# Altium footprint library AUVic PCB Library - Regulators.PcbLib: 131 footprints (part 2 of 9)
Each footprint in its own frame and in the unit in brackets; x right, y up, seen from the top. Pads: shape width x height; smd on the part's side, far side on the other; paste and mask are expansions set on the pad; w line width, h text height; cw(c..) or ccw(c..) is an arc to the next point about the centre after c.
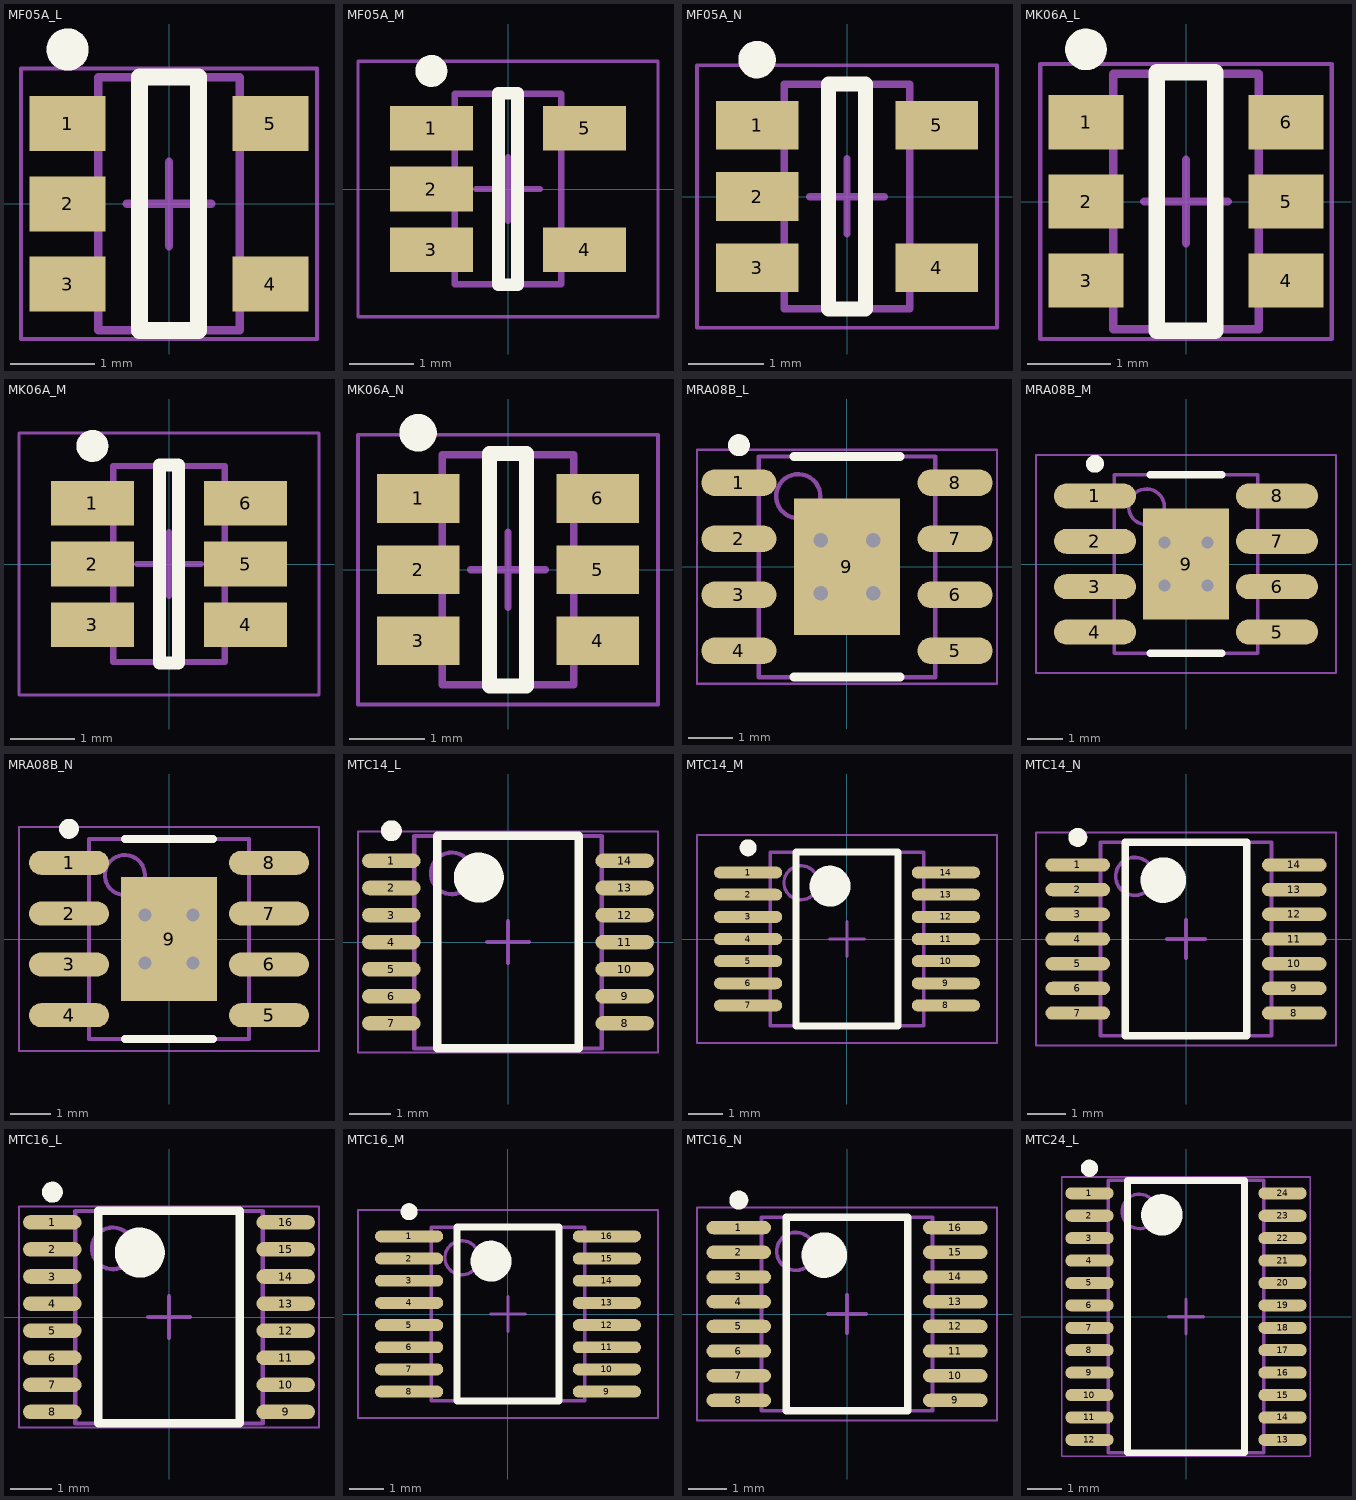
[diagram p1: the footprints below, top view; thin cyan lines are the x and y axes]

## MF05A_L [mm] "SOT23, 5-Leads, Body 2.9x1.6mm, Pitch 0.95mm, Lead Span 2.8mm, IPC High Density"
height 1.19
pads (5):
  rect 0.9x0.65 smd: 1(-1.2,0.95) 2(-1.2,0) 3(-1.2,-0.95) 4(1.2,-0.95) 5(1.2,0.95)
Top Overlay:
  circle w0.25: c-1.2,1.825 r0.125
  lines w0.2: -0.35,-1.5 -0.35,1.5 0.35,1.5 0.35,-1.5 -0.35,-1.5
Mechanical 13:
  lines w0.1: -0.835,-1.495 0.835,-1.495 0.835,1.495 -0.835,1.495 -0.835,-1.495
Mechanical 15:
  lines w0.05: -1.75,-1.6 1.75,-1.6 1.75,1.6 -1.75,1.6 -1.75,-1.6
  lines w0.1: -0.5,0 0.5,0 ; 0,-0.5 0,0.5
3D body: height 1.19, standoff 0.05, extent -0.835,-1.495 0.835,1.495

## MF05A_M [mm] "SOT23, 5-Leads, Body 2.9x1.6mm, Pitch 0.95mm, Lead Span 2.8mm, IPC Low Density"
height 1.19
pads (5):
  rect 1.3x0.7 smd: 1(-1.2,0.95) 2(-1.2,0) 3(-1.2,-0.95) 4(1.2,-0.95) 5(1.2,0.95)
Top Overlay:
  circle w0.25: c-1.2,1.85 r0.125
  lines w0.2: -0.15,-1.5 -0.15,1.5 0.15,1.5 0.15,-1.5 -0.15,-1.5
Mechanical 13:
  lines w0.1: -0.835,-1.495 0.835,-1.495 0.835,1.495 -0.835,1.495 -0.835,-1.495
Mechanical 15:
  lines w0.05: -2.35,-2 2.35,-2 2.35,2 -2.35,2 -2.35,-2
  lines w0.1: -0.5,0 0.5,0 ; 0,-0.5 0,0.5
3D body: height 1.19, standoff 0.05, extent -0.835,-1.495 0.835,1.495

## MF05A_N [mm] "SOT23, 5-Leads, Body 2.9x1.6mm, Pitch 0.95mm, Lead Span 2.8mm, IPC Medium Density"
height 1.19
pads (5):
  rect 1.1x0.65 smd: 1(-1.2,0.95) 2(-1.2,0) 3(-1.2,-0.95) 4(1.2,-0.95) 5(1.2,0.95)
Top Overlay:
  circle w0.25: c-1.2,1.825 r0.125
  lines w0.2: -0.25,-1.5 -0.25,1.5 0.25,1.5 0.25,-1.5 -0.25,-1.5
Mechanical 13:
  lines w0.1: -0.835,-1.495 0.835,-1.495 0.835,1.495 -0.835,1.495 -0.835,-1.495
Mechanical 15:
  lines w0.05: -2,-1.75 2,-1.75 2,1.75 -2,1.75 -2,-1.75
  lines w0.1: -0.5,0 0.5,0 ; 0,-0.5 0,0.5
3D body: height 1.19, standoff 0.05, extent -0.835,-1.495 0.835,1.495

## MK06A_L [mm] "SOT23, 6-Leads, Body 3.0x1.7mm, Pitch 0.95mm, Lead Span 2.9mm, IPC High Density"
height 1
pads (6):
  rect 0.9x0.65 smd: 1(-1.2,0.95) 2(-1.2,0) 3(-1.2,-0.95) 4(1.2,-0.95) 5(1.2,0) 6(1.2,0.95)
Top Overlay:
  circle w0.25: c-1.2,1.825 r0.125
  lines w0.2: -0.35,-1.55 -0.35,1.55 0.35,1.55 0.35,-1.55 -0.35,-1.55
Mechanical 13:
  lines w0.1: -0.875,-1.535 0.875,-1.535 0.875,1.535 -0.875,1.535 -0.875,-1.535
Mechanical 15:
  lines w0.05: -1.75,-1.65 1.75,-1.65 1.75,1.65 -1.75,1.65 -1.75,-1.65
  lines w0.1: -0.5,0 0.5,0 ; 0,-0.5 0,0.5
3D body: height 1, standoff 0.01, extent -0.875,-1.535 0.875,1.535

## MK06A_M [mm] "SOT23, 6-Leads, Body 3.0x1.7mm, Pitch 0.95mm, Lead Span 2.9mm, IPC Low Density"
height 1
pads (6):
  rect 1.3x0.7 smd: 1(-1.2,0.95) 2(-1.2,0) 3(-1.2,-0.95) 4(1.2,-0.95) 5(1.2,0) 6(1.2,0.95)
Top Overlay:
  circle w0.25: c-1.2,1.85 r0.125
  lines w0.2: -0.15,-1.55 -0.15,1.55 0.15,1.55 0.15,-1.55 -0.15,-1.55
Mechanical 13:
  lines w0.1: -0.875,-1.535 0.875,-1.535 0.875,1.535 -0.875,1.535 -0.875,-1.535
Mechanical 15:
  lines w0.05: -2.35,-2.05 2.35,-2.05 2.35,2.05 -2.35,2.05 -2.35,-2.05
  lines w0.1: -0.5,0 0.5,0 ; 0,-0.5 0,0.5
3D body: height 1, standoff 0.01, extent -0.875,-1.535 0.875,1.535

## MK06A_N [mm] "SOT23, 6-Leads, Body 3.0x1.7mm, Pitch 0.95mm, Lead Span 2.9mm, IPC Medium Density"
height 1
pads (6):
  rect 1.1x0.65 smd: 1(-1.2,0.95) 2(-1.2,0) 3(-1.2,-0.95) 4(1.2,-0.95) 5(1.2,0) 6(1.2,0.95)
Top Overlay:
  circle w0.25: c-1.2,1.825 r0.125
  lines w0.2: -0.25,-1.55 -0.25,1.55 0.25,1.55 0.25,-1.55 -0.25,-1.55
Mechanical 13:
  lines w0.1: -0.875,-1.535 0.875,-1.535 0.875,1.535 -0.875,1.535 -0.875,-1.535
Mechanical 15:
  lines w0.05: -2,-1.8 2,-1.8 2,1.8 -2,1.8 -2,-1.8
  lines w0.1: -0.5,0 0.5,0 ; 0,-0.5 0,0.5
3D body: height 1, standoff 0.01, extent -0.875,-1.535 0.875,1.535

## MRA08B_L [mm] "SOIC, 8-Leads, Body 4.9x3.9mm, Pitch 1.27mm, Exposed Pad, IPC High Density"
height 1.68
pads (9):
  oval 1.7x0.6 smd: 1(-2.45,1.905) 2(-2.45,0.635) 3(-2.45,-0.635) 4(-2.45,-1.905) 5(2.45,-1.905) 6(2.45,-0.635) 7(2.45,0.635) 8(2.45,1.905)
  rect 2.41x3.1 smd: 9(0,0)
via -0.6,0.6 diameter 0.66 hole 0.33
via 0.6,0.6 diameter 0.66 hole 0.33
via 0.6,-0.6 diameter 0.66 hole 0.33
via -0.6,-0.6 diameter 0.66 hole 0.33
Top Overlay:
  circle w0.25: c-2.45,2.755 r0.125
  lines w0.2: -1.2,-2.5 1.2,-2.5 ; -1.2,2.5 1.2,2.5
Mechanical 13:
  circle w0.1: c-1.105,1.6 r0.5
  lines w0.1: -2.005,-2.5 -2.005,2.5 2.005,2.5 2.005,-2.5 -2.005,-2.5
Mechanical 15:
  lines w0.05: -3.4,-2.65 -3.4,2.65 3.4,2.65 3.4,-2.65 -3.4,-2.65
  lines w0.1: -0.5,0 0.5,0 ; 0,-0.5 0,0.5
3D body: height 1.68, standoff 0.03, extent -2.005,-2.5 2.005,2.5

## MRA08B_M [mm] "SOIC, 8-Leads, Body 4.9x3.9mm, Pitch 1.27mm, Thermal Pad, IPC Low Density"
height 1.68
pads (9):
  oval 2.3x0.7 smd: 1(-2.55,1.905) 2(-2.55,0.635) 3(-2.55,-0.635) 4(-2.55,-1.905) 5(2.55,-1.905) 6(2.55,-0.635) 7(2.55,0.635) 8(2.55,1.905)
  rect 2.41x3.1 smd: 9(0,0)
via -0.6,0.6 diameter 0.66 hole 0.33
via 0.6,0.6 diameter 0.66 hole 0.33
via 0.6,-0.6 diameter 0.66 hole 0.33
via -0.6,-0.6 diameter 0.66 hole 0.33
Top Overlay:
  circle w0.25: c-2.55,2.805 r0.125
  lines w0.2: -1,-2.5 1,-2.5 ; -1,2.5 1,2.5
Mechanical 13:
  circle w0.1: c-1.105,1.6 r0.5
  lines w0.1: -2.005,-2.5 -2.005,2.5 2.005,2.5 2.005,-2.5 -2.005,-2.5
Mechanical 15:
  lines w0.05: -4.2,-3.05 -4.2,3.05 4.2,3.05 4.2,-3.05 -4.2,-3.05
  lines w0.1: -0.5,0 0.5,0 ; 0,-0.5 0,0.5
3D body: height 1.68, standoff 0.03, extent -2.005,-2.5 2.005,2.5

## MRA08B_N [mm] "SOIC, 8-Leads, Body 4.9x3.9mm, Pitch 1.27mm, Exposed Pad, IPC Medium Density"
height 1.68
pads (9):
  oval 2x0.6 smd: 1(-2.5,1.905) 2(-2.5,0.635) 3(-2.5,-0.635) 4(-2.5,-1.905) 5(2.5,-1.905) 6(2.5,-0.635) 7(2.5,0.635) 8(2.5,1.905)
  rect 2.41x3.1 smd: 9(0,0)
via -0.6,0.6 diameter 0.66 hole 0.33
via 0.6,0.6 diameter 0.66 hole 0.33
via 0.6,-0.6 diameter 0.66 hole 0.33
via -0.6,-0.6 diameter 0.66 hole 0.33
Top Overlay:
  circle w0.25: c-2.5,2.755 r0.125
  lines w0.2: -1.1,-2.5 1.1,-2.5 ; -1.1,2.5 1.1,2.5
Mechanical 13:
  circle w0.1: c-1.105,1.6 r0.5
  lines w0.1: -2.005,-2.5 2.005,-2.5 2.005,2.5 -2.005,2.5 -2.005,-2.5
Mechanical 15:
  lines w0.05: -3.75,-2.8 3.75,-2.8 3.75,2.8 -3.75,2.8 -3.75,-2.8
  lines w0.1: -0.5,0 0.5,0 ; 0,-0.5 0,0.5
3D body: height 1.68, standoff 0.03, extent -2.005,-2.5 2.005,2.5

## MTC14_L [mm] "TSOP, 14-Leads, Body 5x4.4mm, Pitch 0.65mm, IPC High Density"
height 1.1
pads (14):
  oval 1.4x0.35 smd: 1(-2.8,1.95) 2(-2.8,1.3) 3(-2.8,0.65) 4(-2.8,0) 5(-2.8,-0.65) 6(-2.8,-1.3) 7(-2.8,-1.95) 8(2.8,-1.95) 9(2.8,-1.3) 10(2.8,-0.65) 11(2.8,0) 12(2.8,0.65) 13(2.8,1.3) 14(2.8,1.95)
Top Overlay:
  circle w0.25: c-2.8,2.675 r0.125
  circle w0.6: c-0.7,1.55 r0.3
  lines w0.2: -1.7,-2.55 -1.7,2.55 1.7,2.55 1.7,-2.55 -1.7,-2.55
Mechanical 13:
  circle w0.1: c-1.35,1.65 r0.5
  lines w0.1: -2.25,-2.55 -2.25,2.55 2.25,2.55 2.25,-2.55 -2.25,-2.55
Mechanical 15:
  lines w0.05: -3.6,-2.65 -3.6,2.65 3.6,2.65 3.6,-2.65 -3.6,-2.65
  lines w0.1: -0.5,0 0.5,0 ; 0,-0.5 0,0.5
3D body: height 1.1, standoff 0.05, extent -2.25,-2.55 2.25,2.55

## MTC14_M [mm] "TSOP, 14-Leads, Body 5x4.4mm, Pitch 0.65mm, IPC Low Density"
height 1.1
pads (14):
  oval 2x0.35 smd: 1(-2.9,1.95) 2(-2.9,1.3) 3(-2.9,0.65) 4(-2.9,0) 5(-2.9,-0.65) 6(-2.9,-1.3) 7(-2.9,-1.95) 8(2.9,-1.95) 9(2.9,-1.3) 10(2.9,-0.65) 11(2.9,0) 12(2.9,0.65) 13(2.9,1.3) 14(2.9,1.95)
Top Overlay:
  circle w0.25: c-2.9,2.675 r0.125
  circle w0.6: c-0.5,1.55 r0.3
  lines w0.2: -1.5,-2.55 -1.5,2.55 1.5,2.55 1.5,-2.55 -1.5,-2.55
Mechanical 13:
  circle w0.1: c-1.35,1.65 r0.5
  lines w0.1: -2.25,-2.55 -2.25,2.55 2.25,2.55 2.25,-2.55 -2.25,-2.55
Mechanical 15:
  lines w0.05: -4.4,-3.05 -4.4,3.05 4.4,3.05 4.4,-3.05 -4.4,-3.05
  lines w0.1: -0.5,0 0.5,0 ; 0,-0.5 0,0.5
3D body: height 1.1, standoff 0.05, extent -2.25,-2.55 2.25,2.55

## MTC14_N [mm] "TSOP, 14-Leads, Body 5x4.4mm, Pitch 0.65mm, IPC Medium Density"
height 1.1
pads (14):
  oval 1.7x0.35 smd: 1(-2.85,1.95) 2(-2.85,1.3) 3(-2.85,0.65) 4(-2.85,0) 5(-2.85,-0.65) 6(-2.85,-1.3) 7(-2.85,-1.95) 8(2.85,-1.95) 9(2.85,-1.3) 10(2.85,-0.65) 11(2.85,0) 12(2.85,0.65) 13(2.85,1.3) 14(2.85,1.95)
Top Overlay:
  circle w0.25: c-2.85,2.675 r0.125
  circle w0.6: c-0.6,1.55 r0.3
  lines w0.2: -1.6,-2.55 -1.6,2.55 1.6,2.55 1.6,-2.55 -1.6,-2.55
Mechanical 13:
  circle w0.1: c-1.35,1.65 r0.5
  lines w0.1: -2.25,-2.55 -2.25,2.55 2.25,2.55 2.25,-2.55 -2.25,-2.55
Mechanical 15:
  lines w0.05: -3.95,-2.8 -3.95,2.8 3.95,2.8 3.95,-2.8 -3.95,-2.8
  lines w0.1: -0.5,0 0.5,0 ; 0,-0.5 0,0.5
3D body: height 1.1, standoff 0.05, extent -2.25,-2.55 2.25,2.55

## MTC16_L [mm] "TSOP, 16-Leads, Body 5x4.4mm, Pitch 0.65mm, IPC High Density"
height 1.1
pads (16):
  oval 1.4x0.35 smd: 1(-2.8,2.275) 2(-2.8,1.625) 3(-2.8,0.975) 4(-2.8,0.325) 5(-2.8,-0.325) 6(-2.8,-0.975) 7(-2.8,-1.625) 8(-2.8,-2.275) 9(2.8,-2.275) 10(2.8,-1.625) 11(2.8,-0.975) 12(2.8,-0.325) 13(2.8,0.325) 14(2.8,0.975) 15(2.8,1.625) 16(2.8,2.275)
Top Overlay:
  circle w0.6: c-0.7,1.55 r0.3
  circle w0.25: c-2.8,3 r0.125
  lines w0.2: -1.7,-2.55 1.7,-2.55 1.7,2.55 -1.7,2.55 -1.7,-2.55
Mechanical 13:
  circle w0.1: c-1.35,1.65 r0.5
  lines w0.1: -2.25,-2.55 2.25,-2.55 2.25,2.55 -2.25,2.55 -2.25,-2.55
Mechanical 15:
  lines w0.05: -3.6,-2.65 3.6,-2.65 3.6,2.65 -3.6,2.65 -3.6,-2.65
  lines w0.1: -0.5,0 0.5,0 ; 0,-0.5 0,0.5
3D body: height 1.1, standoff 0.05, extent -2.25,-2.55 2.25,2.55

## MTC16_M [mm] "TSOP, 16-Leads, Body 5x4.4mm, Pitch 0.65mm, IPC Low Density"
height 1.1
pads (16):
  oval 2x0.35 smd: 1(-2.9,2.275) 2(-2.9,1.625) 3(-2.9,0.975) 4(-2.9,0.325) 5(-2.9,-0.325) 6(-2.9,-0.975) 7(-2.9,-1.625) 8(-2.9,-2.275) 9(2.9,-2.275) 10(2.9,-1.625) 11(2.9,-0.975) 12(2.9,-0.325) 13(2.9,0.325) 14(2.9,0.975) 15(2.9,1.625) 16(2.9,2.275)
Top Overlay:
  circle w0.25: c-2.9,3 r0.125
  circle w0.6: c-0.5,1.55 r0.3
  lines w0.2: -1.5,-2.55 -1.5,2.55 1.5,2.55 1.5,-2.55 -1.5,-2.55
Mechanical 13:
  circle w0.1: c-1.35,1.65 r0.5
  lines w0.1: -2.25,-2.55 -2.25,2.55 2.25,2.55 2.25,-2.55 -2.25,-2.55
Mechanical 15:
  lines w0.05: -4.4,-3.05 -4.4,3.05 4.4,3.05 4.4,-3.05 -4.4,-3.05
  lines w0.1: -0.5,0 0.5,0 ; 0,-0.5 0,0.5
3D body: height 1.1, standoff 0.05, extent -2.25,-2.55 2.25,2.55

## MTC16_N [mm] "TSOP, 16-Leads, Body 5x4.4mm, Pitch 0.65mm, IPC Medium Density"
height 1.1
pads (16):
  oval 1.7x0.35 smd: 1(-2.85,2.275) 2(-2.85,1.625) 3(-2.85,0.975) 4(-2.85,0.325) 5(-2.85,-0.325) 6(-2.85,-0.975) 7(-2.85,-1.625) 8(-2.85,-2.275) 9(2.85,-2.275) 10(2.85,-1.625) 11(2.85,-0.975) 12(2.85,-0.325) 13(2.85,0.325) 14(2.85,0.975) 15(2.85,1.625) 16(2.85,2.275)
Top Overlay:
  circle w0.25: c-2.85,3 r0.125
  circle w0.6: c-0.6,1.55 r0.3
  lines w0.2: -1.6,-2.55 -1.6,2.55 1.6,2.55 1.6,-2.55 -1.6,-2.55
Mechanical 13:
  circle w0.1: c-1.35,1.65 r0.5
  lines w0.1: -2.25,-2.55 -2.25,2.55 2.25,2.55 2.25,-2.55 -2.25,-2.55
Mechanical 15:
  lines w0.05: -3.95,-2.8 -3.95,2.8 3.95,2.8 3.95,-2.8 -3.95,-2.8
  lines w0.1: -0.5,0 0.5,0 ; 0,-0.5 0,0.5
3D body: height 1.1, standoff 0.05, extent -2.25,-2.55 2.25,2.55

## MTC24_L [mm] "TSOP, 24-Leads, Body 7.8x4.4mm, Pitch 0.65mm, IPC High Density"
height 1.1
pads (24):
  oval 1.4x0.35 smd: 1(-2.8,3.575) 2(-2.8,2.925) 3(-2.8,2.275) 4(-2.8,1.625) 5(-2.8,0.975) 6(-2.8,0.325) 7(-2.8,-0.325) 8(-2.8,-0.975) 9(-2.8,-1.625) 10(-2.8,-2.275) 11(-2.8,-2.925) 12(-2.8,-3.575) 13(2.8,-3.575) 14(2.8,-2.925) 15(2.8,-2.275) 16(2.8,-1.625) 17(2.8,-0.975) 18(2.8,-0.325) 19(2.8,0.325) 20(2.8,0.975) 21(2.8,1.625) 22(2.8,2.275) 23(2.8,2.925) 24(2.8,3.575)
Top Overlay:
  circle w0.6: c-0.7,2.95 r0.3
  circle w0.25: c-2.8,4.3 r0.125
  lines w0.2: -1.7,-3.95 1.7,-3.95 1.7,3.95 -1.7,3.95 -1.7,-3.95
Mechanical 13:
  circle w0.1: c-1.35,3.05 r0.5
  lines w0.1: -2.25,-3.95 2.25,-3.95 2.25,3.95 -2.25,3.95 -2.25,-3.95
Mechanical 15:
  lines w0.05: -3.6,-4.05 3.6,-4.05 3.6,4.05 -3.6,4.05 -3.6,-4.05
  lines w0.1: -0.5,0 0.5,0 ; 0,-0.5 0,0.5
3D body: height 1.1, standoff 0.05, extent -2.25,-3.95 2.25,3.95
